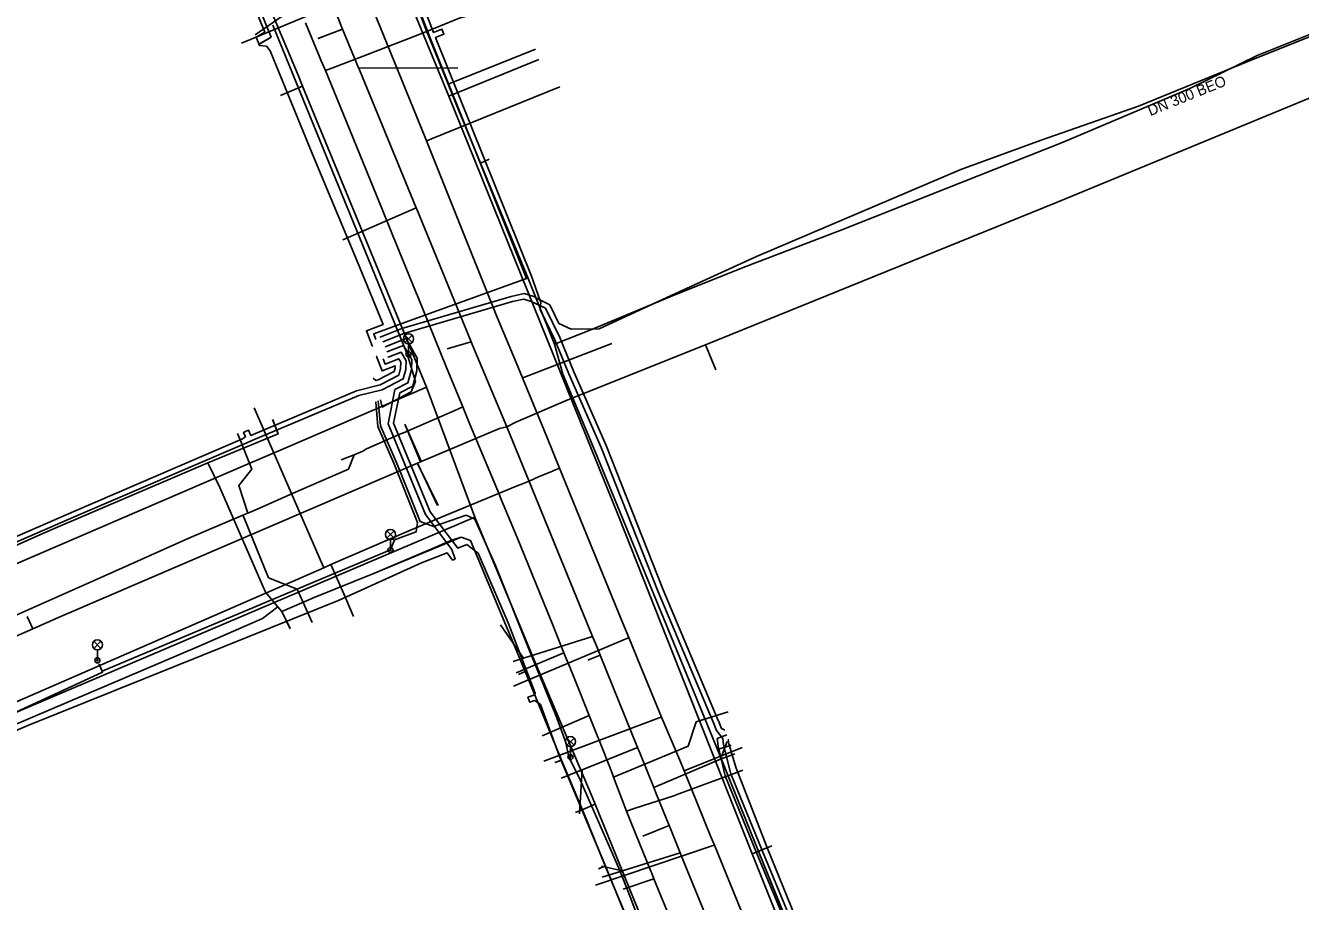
# Model space of a CAD drawing. Extents: x -596228 to -595156, y -1161235 to -1159373.
# Drawn here: x -595753.6 to -595658.7, y -1160560.5 to -1160495.3 of the extents above; entities that cross this region are included whole.
import ezdxf

# ---------------------------------------------------------------- set-up
doc = ezdxf.new("R2010")
doc.units = 0
for name, color, linetype in [('Vrstva 1', 7, 'Continuous'), ('Vrstva 12', 7, 'Continuous'), ('Vrstva 14', 7, 'Continuous'), ('Vrstva 19', 7, 'Continuous'), ('Vrstva 33', 7, 'Continuous'), ('Vrstva 42', 7, 'Continuous'), ('Vrstva 5', 7, 'Continuous'), ('Vrstva 55', 7, 'Continuous'), ('Vrstva 58', 7, 'Continuous'), ('Vrstva 9', 7, 'Continuous')]:
    doc.layers.add(name, color=color, linetype=linetype)

msp = doc.modelspace()

# ---------------------------------------------------------------- linework, layer by layer
at = {"layer": 'Vrstva 1'}
for p, q in [((-595731.86, -1160496.25), (-595730.017, -1160495.546)), ((-595731.826, -1160496.237), (-595730.016, -1160495.546)), ((-595730.01, -1160511.25), (-595724.541, -1160508.863)), ((-595722.232, -1160519.35), (-595720.437, -1160518.843)), ((-595722.22, -1160519.35), (-595720.437, -1160518.843)), ((-595725.39, -1160524.96), (-595724.137, -1160527.759)), ((-595725.39, -1160524.96), (-595724.215, -1160527.768)), ((-595722.94, -1160531.02), (-595724.437, -1160527.873)), ((-595722.893, -1160531.02), (-595724.431, -1160527.883)), ((-595718.27, -1160539.9), (-595716.54, -1160542.4)), ((-595701.39, -1160548.6), (-595701.888, -1160549.918)), ((-595712.39, -1160553.97), (-595712.18, -1160550.7)), ((-595707.67, -1160555.65), (-595705.703, -1160554.846)), ((-595707.67, -1160555.65), (-595705.7, -1160554.85)), ((-595710.75, -1160557.88), (-595709.19, -1160558.23))]:
    msp.add_line(p, q, dxfattribs=at)
at = {"layer": 'Vrstva 12'}
for p, q in [((-595733.33, -1160498.97), (-595742.02, -1160478.25)), ((-595722.16, -1160499.64), (-595715.71, -1160497.06)), ((-595722.12, -1160500.55), (-595715.4, -1160497.82)), ((-595732.99, -1160499.8), (-595733.33, -1160498.97)), ((-595722.87, -1160498.69), (-595722.12, -1160500.55)), ((-595732.99, -1160499.8), (-595734.65, -1160500.49)), ((-595723.76, -1160522.22), (-595732.99, -1160499.8)), ((-595722.16, -1160499.64), (-595721.55, -1160501.14)), ((-595721.55, -1160501.14), (-595719.76, -1160505.53)), ((-595719.76, -1160505.53), (-595719.11, -1160505.24)), ((-595719.76, -1160505.53), (-595718.99, -1160507.4)), ((-595734.23, -1160526.73), (-595723.76, -1160522.22)), ((-595723.76, -1160522.22), (-595720.17, -1160531.9)), ((-595737.26, -1160528.03), (-595734.23, -1160526.73)), ((-595771.89, -1160542.93), (-595737.26, -1160528.03)), ((-595734.53, -1160538.91), (-595733.92, -1160540.21)), ((-595716.42, -1160543.38), (-595716.93, -1160543.6)), ((-595713.72, -1160549.98), (-595716.42, -1160543.38)), ((-595702.1, -1160549.2), (-595701.09, -1160548.86)), ((-595713.72, -1160549.98), (-595714.22, -1160550.16)), ((-595711.21, -1160553.27), (-595711.44, -1160552.71)), ((-595712.13, -1160553.65), (-595712.69, -1160553.88)), ((-595711.21, -1160553.27), (-595712.13, -1160553.65)), ((-595700.73, -1160578.97), (-595711.21, -1160553.27)), ((-595699.54, -1160556.96), (-595698.06, -1160556.37)), ((-595699.54, -1160556.96), (-595691.57, -1160576.72)), ((-595710.46, -1160557.86), (-595710.95, -1160558.07)), ((-595707.56, -1160564.85), (-595710.46, -1160557.86))]:
    msp.add_line(p, q, dxfattribs=at)
for points in [[(-595745.28, -1160444.11), (-595734.95, -1160469.37), (-595722.87, -1160498.69)], [(-595728.56, -1160483.67), (-595725.45, -1160491.2), (-595723.88, -1160495.43), (-595722.16, -1160499.64)], [(-595736.24, -1160496.68), (-595735.34, -1160496.14), (-595738.79, -1160487.69)], [(-595650.62, -1160493.21), (-595656.73, -1160495.43), (-595661.93, -1160497.51), (-595666.94, -1160499.96), (-595676.38, -1160503.96), (-595692.86, -1160510.49), (-595700.31, -1160513.35), (-595705.57, -1160515.46), (-595711.53, -1160517.94), (-595714.24, -1160519)], [(-595699.54, -1160556.96), (-595709.46, -1160531.87), (-595722.12, -1160500.55)], [(-595718.99, -1160507.4), (-595716.19, -1160514.13), (-595714.24, -1160519)], [(-595714.24, -1160519), (-595713.61, -1160521.25), (-595711.25, -1160526.95), (-595702.1, -1160549.2)], [(-595740.05, -1160527.85), (-595734.82, -1160525.69), (-595735.22, -1160524.65)], [(-595753.45, -1160533.6), (-595751.89, -1160532.9), (-595742.31, -1160528.82), (-595740.05, -1160527.85)], [(-595734.53, -1160538.91), (-595734.84, -1160538.56), (-595735.76, -1160537.48), (-595739.15, -1160529.69), (-595740.05, -1160527.85)], [(-595720.17, -1160531.9), (-595759.49, -1160548.61), (-595781.21, -1160557.97)], [(-595711.44, -1160552.71), (-595715.73, -1160542.59), (-595720.17, -1160531.9)], [(-595755.8, -1160534.64), (-595755.11, -1160534.35), (-595753.45, -1160533.6)], [(-595716.42, -1160543.38), (-595720.5, -1160533.62), (-595721.19, -1160533.39), (-595721.89, -1160533.6), (-595723.19, -1160534.18), (-595727.63, -1160536.05), (-595732.13, -1160537.87), (-595734.53, -1160538.91)], [(-595702.1, -1160549.2), (-595699.08, -1160556.72), (-595696.19, -1160563.86)], [(-595710.46, -1160557.86), (-595712.1, -1160553.81), (-595713.72, -1160549.98)]]:
    msp.add_lwpolyline(points, dxfattribs=at)
at = {"layer": 'Vrstva 14'}
msp.add_line((-595714.13, -1160528.35), (-595713.88, -1160528.24), dxfattribs=at)
for points in [[(-595728.289, -1160492.738), (-595728.43, -1160492.798), (-595737.537, -1160496.608)], [(-595713.88, -1160528.24), (-595714.81, -1160525.9), (-595716.62, -1160521.51), (-595717.09, -1160520.37), (-595718.53, -1160516.95), (-595721.63, -1160509.2), (-595723.76, -1160503.88), (-595723.87, -1160503.61), (-595726.14, -1160498.01), (-595728.289, -1160492.738)], [(-595723.76, -1160503.88), (-595723.623, -1160503.826), (-595723.39, -1160503.73), (-595713.835, -1160499.86)], [(-595716.62, -1160521.51), (-595716.48, -1160521.46), (-595709.981, -1160518.962)], [(-595731.419, -1160535.66), (-595731.52, -1160535.428), (-595736.607, -1160523.74)], [(-595725.125, -1160532.921), (-595722.74, -1160531.91), (-595717.02, -1160529.56), (-595716.63, -1160529.4), (-595716.12, -1160529.2), (-595715.38, -1160528.87), (-595714.56, -1160528.54), (-595714.13, -1160528.35)], [(-595684.49, -1160600.24), (-595686.78, -1160594.64), (-595688.705, -1160590.004), (-595689.08, -1160589.1), (-595690.321, -1160586.062), (-595691.34, -1160583.57), (-595691.73, -1160582.6), (-595693.57, -1160578), (-595695.71, -1160572.74), (-595695.84, -1160572.43), (-595696.57, -1160570.643), (-595698.08, -1160566.82), (-595700.244, -1160561.435), (-595700.32, -1160561.25), (-595702.343, -1160556.317), (-595702.6, -1160555.69), (-595704.585, -1160550.782), (-595704.91, -1160549.98), (-595706.28, -1160546.77), (-595707.84, -1160542.98), (-595708.71, -1160540.86), (-595709.28, -1160539.49), (-595711.57, -1160533.91), (-595713.88, -1160528.24)], [(-595837.187, -1160580.987), (-595835.184, -1160580.128), (-595817.742, -1160572.699), (-595814.419, -1160571.284), (-595810.464, -1160569.6), (-595805.025, -1160567.274), (-595804.67, -1160567.132), (-595791.445, -1160561.5), (-595791.248, -1160561.416), (-595772.235, -1160553.319), (-595771.912, -1160553.183), (-595771.773, -1160553.123), (-595770.533, -1160552.594), (-595769.841, -1160552.299), (-595760.944, -1160548.51), (-595758.144, -1160547.292), (-595731.419, -1160535.66), (-595730.881, -1160535.426), (-595725.125, -1160532.921)], [(-595730.881, -1160535.426), (-595729.935, -1160537.6), (-595729.203, -1160539.282)], [(-595708.71, -1160540.86), (-595708.848, -1160540.916), (-595717.294, -1160544.478)], [(-595706.28, -1160546.77), (-595706.443, -1160546.829), (-595715.041, -1160550.046)], [(-595704.585, -1160550.782), (-595704.455, -1160550.73), (-595700.266, -1160549.031)], [(-595702.343, -1160556.317), (-595702.498, -1160556.369), (-595711.196, -1160559.292)]]:
    msp.add_lwpolyline(points, dxfattribs=at)
at = {"layer": 'Vrstva 19'}
for p, q in [((-595713.54, -1160541.99), (-595717.1, -1160543.48)), ((-595703.69, -1160547.13), (-595701.32, -1160546.39)), ((-595711.66, -1160546.65), (-595715.15, -1160548.17)), ((-595706.84, -1160558.81), (-595709.142, -1160559.58))]:
    msp.add_line(p, q, dxfattribs=at)
for points in [[(-595731.29, -1160498.62), (-595730.82, -1160498.45), (-595728.49, -1160497.56), (-595724.32, -1160495.95), (-595721.27, -1160494.71), (-595718.31, -1160493.93)], [(-595708.87, -1160553.78), (-595709.85, -1160551.24), (-595709.96, -1160550.95), (-595710.971, -1160548.37), (-595711.01, -1160548.27), (-595711.06, -1160548.14), (-595711.66, -1160546.65), (-595712.69, -1160544.1), (-595712.74, -1160543.97), (-595713.161, -1160542.93), (-595713.44, -1160542.24), (-595713.54, -1160541.99), (-595713.7, -1160541.61), (-595714.45, -1160539.74), (-595714.52, -1160539.57), (-595717.01, -1160533.41), (-595718.25, -1160530.44), (-595718.34, -1160530.23), (-595720.56, -1160524.91), (-595721.07, -1160523.68), (-595722.27, -1160520.74), (-595724.45, -1160515.41), (-595724.55, -1160515.18), (-595726.29, -1160510.86), (-595727.17, -1160508.71), (-595727.24, -1160508.54), (-595730.22, -1160501.25), (-595731.29, -1160498.62), (-595731.63, -1160497.86), (-595731.71, -1160497.66), (-595732.77, -1160495.09)], [(-595721.07, -1160523.68), (-595721.67, -1160523.95), (-595725.49, -1160525.61), (-595725.63, -1160525.67), (-595728.24, -1160526.81), (-595728.52, -1160526.98), (-595729.16, -1160527.24), (-595730.13, -1160527.63)], [(-595737.08, -1160531.58), (-595737.73, -1160529.52), (-595736.77, -1160528.32), (-595737.22, -1160527.19), (-595737.57, -1160526.31), (-595737.83, -1160525.66)], [(-595729.16, -1160527.24), (-595729.58, -1160528.31), (-595733.69, -1160530.1), (-595736.21, -1160531.22), (-595736.37, -1160531.29), (-595737.08, -1160531.58), (-595737.44, -1160531.73), (-595741.47, -1160533.46), (-595747.83, -1160536.31), (-595755.67, -1160539.78)], [(-595737.44, -1160531.73), (-595737.32, -1160532.02), (-595735.53, -1160536.4), (-595733.4, -1160537.25), (-595732.27, -1160539.74)], [(-595709.85, -1160551.24), (-595708.231, -1160550.567), (-595704.29, -1160548.93), (-595703.69, -1160547.13)], [(-595708.87, -1160553.78), (-595708.23, -1160553.55), (-595705.37, -1160552.63), (-595704.98, -1160552.49), (-595703.1, -1160551.8), (-595700.68, -1160550.901), (-595700.22, -1160550.73)], [(-595705.5, -1160562.07), (-595706.84, -1160558.81), (-595707.03, -1160558.34), (-595707.07, -1160558.24), (-595708.54, -1160554.64), (-595708.87, -1160553.78)]]:
    msp.add_lwpolyline(points, dxfattribs=at)
at = {"layer": 'Vrstva 33'}
for p, q in [((-595725.375, -1160518.345), (-595724.845, -1160518.875)), ((-595725.375, -1160518.875), (-595724.845, -1160518.345)), ((-595725.11, -1160519.76), (-595725.11, -1160518.985)), ((-595726.715, -1160532.915), (-595726.185, -1160533.445)), ((-595726.715, -1160533.445), (-595726.185, -1160532.915)), ((-595726.45, -1160534.33), (-595726.45, -1160533.555)), ((-595748.535, -1160541.135), (-595748.005, -1160541.665)), ((-595748.535, -1160541.665), (-595748.005, -1160541.135)), ((-595748.27, -1160542.55), (-595748.27, -1160541.775)), ((-595713.315, -1160548.335), (-595712.785, -1160548.865)), ((-595713.315, -1160548.865), (-595712.785, -1160548.335)), ((-595713.05, -1160549.75), (-595713.05, -1160548.975))]:
    msp.add_line(p, q, dxfattribs=at)
for centre, radius in [((-595725.11, -1160518.61), 0.375), ((-595725.11, -1160519.76), 0.19), ((-595725.11, -1160519.76), 0.05), ((-595726.45, -1160533.18), 0.375), ((-595726.45, -1160534.33), 0.19), ((-595726.45, -1160534.33), 0.05), ((-595748.27, -1160541.4), 0.375), ((-595748.27, -1160542.55), 0.19), ((-595748.27, -1160542.55), 0.05), ((-595713.05, -1160548.6), 0.375), ((-595713.05, -1160549.75), 0.19), ((-595713.05, -1160549.75), 0.05)]:
    msp.add_circle(centre, radius, dxfattribs=at)
at = {"layer": 'Vrstva 42'}
for points in [[(-595725.345, -1160491.44), (-595723.532, -1160496.16), (-595716.319, -1160514.111), (-595725.339, -1160517.365), (-595727.7, -1160518.244), (-595727.535, -1160518.661)], [(-595725.031, -1160491.135), (-595723.237, -1160495.798), (-595722.62, -1160495.549), (-595722.545, -1160495.735), (-595722.47, -1160495.92), (-595723.096, -1160496.173), (-595715.962, -1160513.956)], [(-595737.119, -1160492.582), (-595735.809, -1160495.779), (-595736.457, -1160496.157), (-595736.352, -1160496.399)], [(-595651.078, -1160493.158), (-595656.247, -1160495.397), (-595662.636, -1160497.954), (-595670.761, -1160501.277), (-595678.017, -1160503.814), (-595684.003, -1160506.01), (-595699.194, -1160512.482), (-595705.568, -1160515.395), (-595710.928, -1160517.878), (-595713.013, -1160517.88), (-595713.911, -1160517.459), (-595714.588, -1160516.083), (-595715.327, -1160515.702), (-595715.791, -1160515.462), (-595716.504, -1160515.241), (-595717.478, -1160515.459), (-595725.6, -1160517.849), (-595727.211, -1160518.481), (-595727.201, -1160518.505)], [(-595736.352, -1160496.399), (-595736.195, -1160496.772), (-595735.691, -1160496.825), (-595735.399, -1160497.156), (-595732.276, -1160504.802), (-595728.938, -1160512.838), (-595726.996, -1160517.538), (-595728.246, -1160518.028), (-595727.809, -1160519.145), (-595727.756, -1160519.124)], [(-595715.962, -1160513.956), (-595715.327, -1160515.702), (-595715.264, -1160515.874), (-595715.285, -1160516.151), (-595715.307, -1160516.435), (-595714.211, -1160518.678), (-595713.164, -1160521.222), (-595710.76, -1160526.712), (-595706.518, -1160537.452), (-595702.41, -1160547.2), (-595702.175, -1160547.78), (-595701.814, -1160548.248), (-595701.72, -1160548.37), (-595701.657, -1160548.85), (-595701.119, -1160550.997), (-595698.787, -1160556.709), (-595695.291, -1160565.147), (-595692.534, -1160571.753), (-595691.807, -1160572.725), (-595691.762, -1160572.739), (-595691.519, -1160572.641)], [(-595727.011, -1160518.832), (-595725.454, -1160518.221), (-595717.368, -1160515.844), (-595716.521, -1160515.655), (-595715.981, -1160515.822), (-595715.285, -1160516.151), (-595714.914, -1160516.327), (-595713.845, -1160518.514), (-595712.796, -1160521.066), (-595710.39, -1160526.558), (-595706.148, -1160537.3), (-595702.049, -1160547.036), (-595702.035, -1160547.054), (-595701.805, -1160547.63), (-595701.613, -1160547.735), (-595701.573, -1160547.719)], [(-595726.858, -1160519.202), (-595725.282, -1160518.598), (-595724.455, -1160520.056), (-595724.49, -1160520.99), (-595724.793, -1160522.133), (-595725.759, -1160522.644), (-595726.216, -1160524.89), (-595723.494, -1160531.49), (-595721.43, -1160534.205), (-595720.762, -1160533.93)], [(-595762.195, -1160537.187), (-595749.865, -1160531.824), (-595737.306, -1160526.437), (-595736.519, -1160526.092), (-595728.819, -1160522.842), (-595727.062, -1160522.397), (-595725.502, -1160521.591), (-595725.311, -1160520.892), (-595725.289, -1160520.251), (-595725.662, -1160519.592), (-595726.627, -1160519.97), (-595726.636, -1160519.948)], [(-595727.734, -1160521.543), (-595727.534, -1160521.706), (-595727.367, -1160521.654), (-595726.181, -1160521.041), (-595726.107, -1160520.771), (-595726.102, -1160520.622), (-595727.08, -1160521.006), (-595727.49, -1160519.932), (-595727.431, -1160519.909)], [(-595726.724, -1160519.574), (-595725.48, -1160519.1), (-595724.874, -1160520.161), (-595724.886, -1160520.931), (-595725.154, -1160521.888), (-595726.121, -1160522.388), (-595726.631, -1160524.933), (-595723.844, -1160531.691), (-595721.885, -1160534.292), (-595721.633, -1160535.018)], [(-595762.353, -1160536.819), (-595750.023, -1160531.456), (-595737.466, -1160526.069), (-595737.249, -1160525.898), (-595737.382, -1160525.574), (-595737.197, -1160525.494), (-595737.014, -1160525.413), (-595736.851, -1160525.802), (-595736.677, -1160525.724), (-595728.97, -1160522.472), (-595727.215, -1160522.025), (-595725.842, -1160521.316), (-595725.709, -1160520.832), (-595725.692, -1160520.35), (-595725.839, -1160520.09), (-595726.853, -1160520.488), (-595727.004, -1160520.101)], [(-595720.762, -1160533.93), (-595719.914, -1160534.58), (-595717.69, -1160539.757), (-595715.677, -1160544.986), (-595715.714, -1160545.117), (-595716.225, -1160545.299), (-595716.142, -1160545.499), (-595716.074, -1160545.674), (-595715.736, -1160545.545), (-595715.609, -1160545.608), (-595715.292, -1160545.848), (-595713.873, -1160549.714), (-595710.536, -1160557.638), (-595708.431, -1160562.803)], [(-595724.132, -1160535.292), (-595722.233, -1160534.535), (-595721.829, -1160535.083), (-595721.633, -1160535.018)], [(-595724.132, -1160535.292), (-595730.28, -1160538.06), (-595740.484, -1160542.194), (-595753.439, -1160547.392), (-595761.019, -1160550.654), (-595769.973, -1160554.603), (-595770.22, -1160554.998), (-595769.919, -1160555.449), (-595770.068, -1160555.68)], [(-595701.423, -1160548.09), (-595701.814, -1160548.248), (-595702.124, -1160548.373), (-595702.048, -1160548.941), (-595701.546, -1160551.152), (-595699.176, -1160556.942), (-595695.641, -1160565.458), (-595692.961, -1160571.87), (-595692.035, -1160573.072), (-595691.747, -1160573.164), (-595691.743, -1160573.163), (-595691.369, -1160573.012)], [(-595691.669, -1160572.27), (-595691.729, -1160572.197), (-595692.262, -1160571.52), (-595694.905, -1160565.107), (-595698.398, -1160556.554), (-595700.73, -1160550.569), (-595701.266, -1160548.759), (-595701.303, -1160548.472), (-595701.273, -1160548.46)]]:
    msp.add_lwpolyline(points, dxfattribs=at)
at = {"layer": 'Vrstva 5'}
msp.add_line((-595736.53, -1160495.98), (-595731.321, -1160492.373), dxfattribs=at)
at = {"layer": 'Vrstva 55'}
for points in [[(-595727.19, -1160523.15), (-595727.07, -1160523.69), (-595724.91, -1160522.55), (-595724.6, -1160521.78), (-595725.16, -1160519.9), (-595725.11, -1160519.76), (-595725.24, -1160519.68), (-595727.83, -1160513.31), (-595731.46, -1160504.44), (-595735.22, -1160495.26)], [(-595727.53, -1160523.3), (-595727.389, -1160525.133), (-595726.202, -1160527.858), (-595724.433, -1160532.287), (-595724.53, -1160532.97), (-595726.15, -1160533.59), (-595726.45, -1160534.33)], [(-595727.36, -1160523.22), (-595727.191, -1160525.087), (-595726.018, -1160527.782), (-595725.687, -1160528.623), (-595724.247, -1160532.213), (-595723.25, -1160532.59), (-595720.81, -1160531.73), (-595720.17, -1160532.05), (-595718.64, -1160535.48), (-595716.09, -1160541.9), (-595715.34, -1160543.71), (-595714.06, -1160546.82), (-595713.39, -1160548.66), (-595713.17, -1160549.76), (-595713.05, -1160549.75), (-595713.11, -1160549.89), (-595712.32, -1160551.44), (-595709.373, -1160558.205), (-595708.617, -1160560.165), (-595707.78, -1160562.309)], [(-595726.45, -1160534.33), (-595747.91, -1160543.35), (-595748.14, -1160542.84), (-595747.88, -1160543.42), (-595759.25, -1160548.68), (-595770.71, -1160553.45), (-595777.92, -1160556), (-595777.99, -1160555.51), (-595777.81, -1160555.95), (-595795.33, -1160563.42), (-595800.43, -1160565.81), (-595800.61, -1160565.1), (-595800.45, -1160565.65), (-595809.38, -1160569.92), (-595816.66, -1160573.28), (-595826.61, -1160577.18), (-595826.71, -1160576.79), (-595826.56, -1160576.99), (-595831.54, -1160578.56), (-595835.02, -1160580.99), (-595835.15, -1160581.82), (-595834.89, -1160583.88), (-595832.76, -1160590.31)]]:
    msp.add_lwpolyline(points, dxfattribs=at)
at = {"layer": 'Vrstva 58'}
for p, q in [((-595722.16, -1160499.64), (-595715.66, -1160497.05)), ((-595722.16, -1160499.64), (-595719.76, -1160505.53)), ((-595734.82, -1160525.69), (-595735.23, -1160524.63)), ((-595740.05, -1160527.85), (-595734.82, -1160525.69)), ((-595734.53, -1160538.91), (-595733.93, -1160540.18)), ((-595716.42, -1160543.38), (-595716.88, -1160543.58)), ((-595713.72, -1160549.98), (-595716.42, -1160543.38)), ((-595702.1, -1160549.2), (-595701.15, -1160548.88)), ((-595713.72, -1160549.98), (-595714.2, -1160550.15)), ((-595710.46, -1160557.86), (-595710.96, -1160558.07)), ((-595707.56, -1160564.85), (-595710.46, -1160557.86))]:
    msp.add_line(p, q, dxfattribs=at)
for points in [[(-595728.56, -1160483.67), (-595725.45, -1160491.2), (-595723.88, -1160495.43), (-595722.16, -1160499.64)], [(-595736.26, -1160496.69), (-595735.34, -1160496.14), (-595738.79, -1160487.69)], [(-595650.62, -1160493.21), (-595656.73, -1160495.43), (-595661.93, -1160497.51), (-595666.94, -1160499.96), (-595676.38, -1160503.96), (-595692.86, -1160510.49), (-595700.31, -1160513.35), (-595705.57, -1160515.46), (-595711.53, -1160517.94), (-595714.24, -1160519)], [(-595719.76, -1160505.53), (-595718.99, -1160507.4), (-595716.19, -1160514.13), (-595714.24, -1160519)], [(-595714.24, -1160519), (-595713.61, -1160521.25), (-595711.25, -1160526.95), (-595702.1, -1160549.2)], [(-595755.8, -1160534.64), (-595755.11, -1160534.35), (-595751.89, -1160532.9), (-595742.31, -1160528.82), (-595740.05, -1160527.85)], [(-595734.53, -1160538.91), (-595734.84, -1160538.56), (-595735.76, -1160537.48), (-595739.15, -1160529.69), (-595740.05, -1160527.85)], [(-595707.56, -1160564.85), (-595710.46, -1160557.86), (-595712.1, -1160553.81), (-595713.72, -1160549.98), (-595716.42, -1160543.38), (-595720.5, -1160533.62), (-595721.19, -1160533.39), (-595727.63, -1160536.05), (-595732.13, -1160537.87), (-595734.53, -1160538.91), (-595734.84, -1160538.56), (-595735.97, -1160539.44), (-595740.69, -1160541.49), (-595753.11, -1160546.77), (-595759.41, -1160549.45)], [(-595716.42, -1160543.38), (-595720.5, -1160533.62), (-595721.19, -1160533.39), (-595721.89, -1160533.6), (-595723.19, -1160534.18), (-595727.63, -1160536.05), (-595732.13, -1160537.87), (-595734.53, -1160538.91)], [(-595702.1, -1160549.2), (-595699.08, -1160556.72), (-595692.22, -1160573.71), (-595690.81, -1160577.51), (-595686.14, -1160589.07)], [(-595710.46, -1160557.86), (-595712.1, -1160553.81), (-595713.72, -1160549.98)]]:
    msp.add_lwpolyline(points, dxfattribs=at)
at = {"layer": 'Vrstva 9'}
for p, q in [((-595648.555, -1160496.753), (-595676.871, -1160508.46)), ((-595721.45, -1160498.46), (-595728.834, -1160498.422)), ((-595702.241, -1160520.909), (-595702.993, -1160519.056)), ((-595726.4, -1160528.72), (-595750.952, -1160539.263)), ((-595753.491, -1160539.283), (-595753.087, -1160540.198)), ((-595711.771, -1160542.54), (-595710.844, -1160542.164))]:
    msp.add_line(p, q, dxfattribs=at)
for points in [[(-595717.79, -1160525.17), (-595720.34, -1160519.076), (-595720.437, -1160518.843), (-595724.502, -1160508.959), (-595724.541, -1160508.863), (-595728.765, -1160498.591), (-595728.834, -1160498.422), (-595729.894, -1160495.844), (-595730.017, -1160495.546), (-595730.35, -1160494.734), (-595730.443, -1160494.509), (-595731.251, -1160492.542), (-595731.321, -1160492.373), (-595733.743, -1160486.484), (-595733.839, -1160486.25), (-595734.001, -1160485.855), (-595734.086, -1160485.649), (-595735.653, -1160481.838), (-595735.667, -1160481.804), (-595736.971, -1160478.645)], [(-595676.871, -1160508.46), (-595702.993, -1160519.056), (-595713.255, -1160523.162)], [(-595713.255, -1160523.162), (-595717.126, -1160524.81), (-595717.79, -1160525.17)], [(-595717.79, -1160525.17), (-595718.33, -1160525.3), (-595724.215, -1160527.768), (-595724.437, -1160527.873), (-595726.4, -1160528.72)], [(-595717.79, -1160525.17), (-595711.409, -1160540.77), (-595711.123, -1160541.475), (-595710.844, -1160542.164), (-595708.06, -1160549.03), (-595707.9, -1160549.426), (-595706.85, -1160552.03), (-595706.693, -1160552.414), (-595705.7, -1160554.85), (-595705.582, -1160555.142), (-595704.88, -1160556.88), (-595704.801, -1160557.073), (-595702.56, -1160562.58), (-595702.532, -1160562.65), (-595700.915, -1160566.467)], [(-595750.952, -1160539.263), (-595753.087, -1160540.198), (-595760.422, -1160543.423), (-595760.903, -1160543.637), (-595761.488, -1160543.894), (-595765.689, -1160545.739), (-595767.013, -1160546.322), (-595776.156, -1160550.347), (-595777.019, -1160550.725), (-595783.232, -1160553.459), (-595784.099, -1160553.84)], [(-595717.32, -1160542.64), (-595716.54, -1160542.4), (-595711.409, -1160540.77)], [(-595713.74, -1160551.33), (-595712.18, -1160550.7), (-595708.06, -1160549.03)], [(-595700.83, -1160549.5), (-595701.888, -1160549.918), (-595706.85, -1160552.03)], [(-595710.69, -1160558.7), (-595709.19, -1160558.23), (-595704.88, -1160556.88)]]:
    msp.add_lwpolyline(points, dxfattribs=at)

# ---------------------------------------------------------------- texts
at = {"layer": 'Vrstva 12'}
msp.add_text('DN 300 BEO', height=0.8, rotation=22, dxfattribs=at).set_placement((-595669.891, -1160502.034))

doc.saveas('drawing.dxf')
